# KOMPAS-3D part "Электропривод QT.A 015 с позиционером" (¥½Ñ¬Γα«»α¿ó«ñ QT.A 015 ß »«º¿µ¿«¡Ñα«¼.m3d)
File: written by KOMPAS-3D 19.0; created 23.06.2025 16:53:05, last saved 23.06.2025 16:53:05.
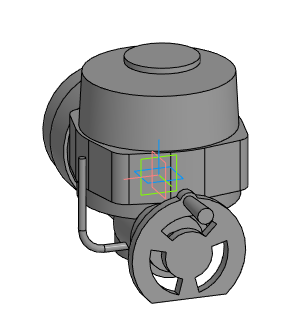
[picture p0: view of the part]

Document properties: Автор: Евгений; Полное имя файла: E:\Dendor Работа Сачек\3D для проектировщиков\3.5 Тип QT.А Электропривод\stp_Электропривод QT.A с позиционером\Электропривод QT.A 015 с позиционером.m3d

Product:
- Part/product: Электропривод QT.A 015 с позиционером

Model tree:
1. Операция без истории:1  (labels: Электропривод QT.A 015 с позиционером)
